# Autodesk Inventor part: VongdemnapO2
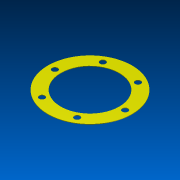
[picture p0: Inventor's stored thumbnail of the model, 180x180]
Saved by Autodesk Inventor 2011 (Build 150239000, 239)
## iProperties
Created: 2011-05
Part Number: VongdemnapO2
Document SubType Name: Modeling
Designer: 904Chiaki
Density: 1 g/cm^3
Author: 904Chiaki
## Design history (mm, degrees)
sketch "Sketch1"
  geometry: C1 r 55 at (-18.756, 2.953); C2 r 79 at (-18.756, 2.953); 1 further point
  constraints: 2 centre point, 1 coincident
  dimensions: "d0" = 110 diameter of C1; "d1" = 158 diameter of C2
extrude "Extrusion1" new body sketch "Sketch1" distance "d2" = 1; taper "d3" = 0 deg
workplane "Work Plane1"
  workaxis "Work Axis1"
node "Hole2"
body "Solid1"
sketch "Sketch2"
  geometry: 6 further points
hole "Hole1" sketch "Sketch2" diameter "d5" = 11; stored, may be unused: countersink angle "d9" = 90 deg, drill point angle "d11" = 0 deg; dims "d6" = 6, "d7" = 4, "d8" = 2, "d10" = 8
other parameters: "d4" = 90 deg
